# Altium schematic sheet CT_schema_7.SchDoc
size 278 x 170 mm
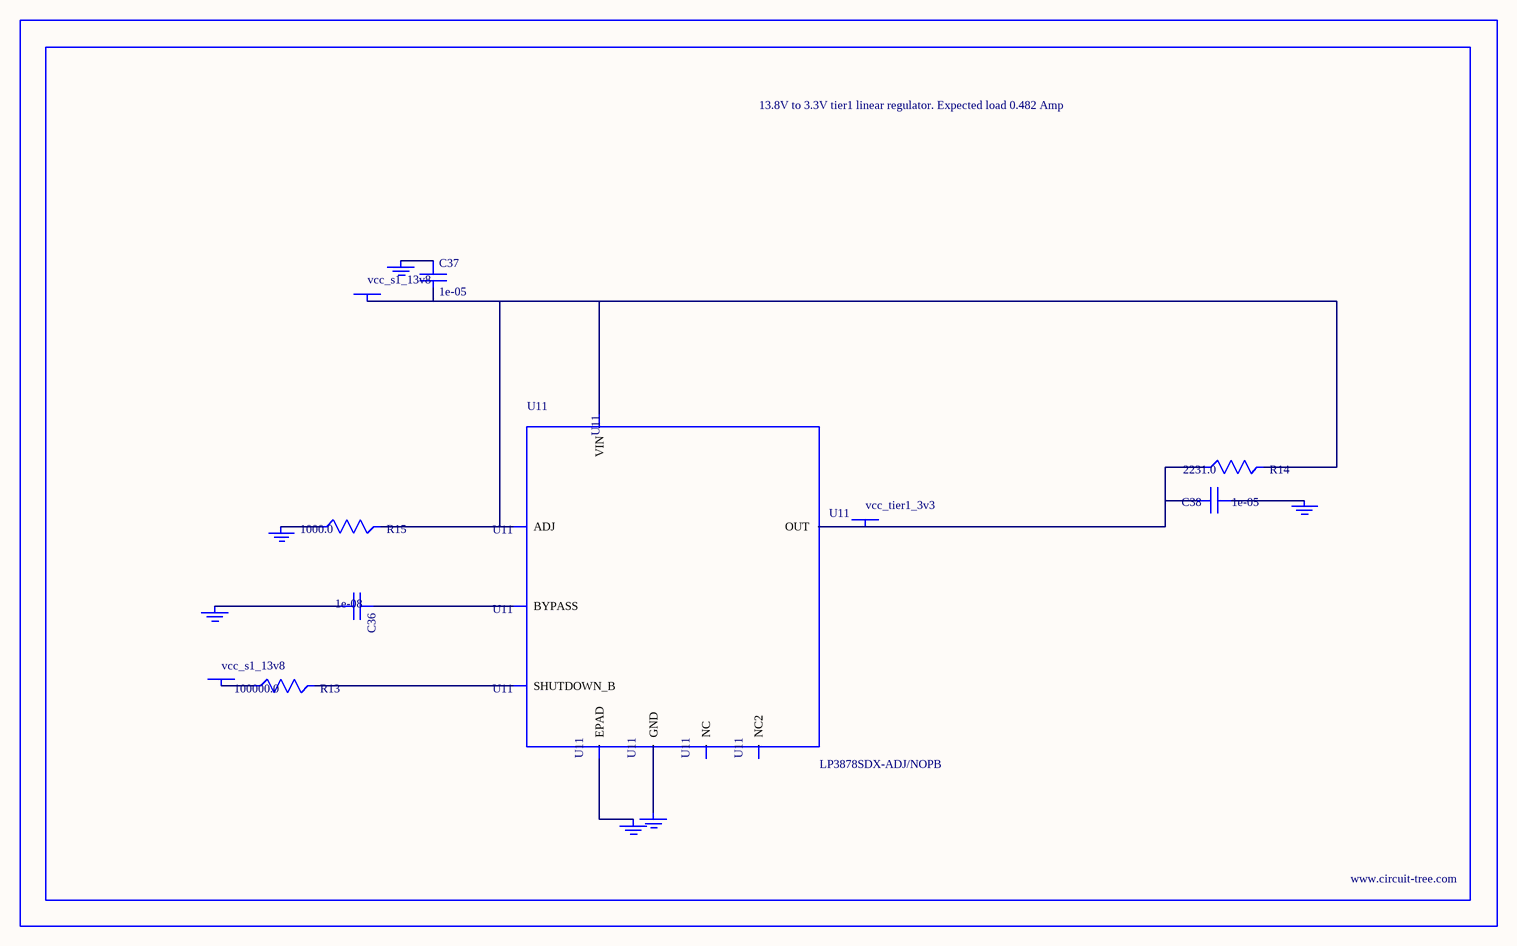
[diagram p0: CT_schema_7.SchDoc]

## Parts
BORDER6  (no value)
C36  1e-08  [C0402]
C37  1e-05  [C1210]
C38  1e-05  [C1210]
GND_INSTANCE_6_0  (no value)
GND_INSTANCE_6_1  (no value)
GND_INSTANCE_6_2  (no value)
GND_INSTANCE_6_3  (no value)
GND_INSTANCE_6_4  (no value)
GND_INSTANCE_6_5  (no value)
POWER_INSTANCE_6_0  vcc_s1_13v8
POWER_INSTANCE_6_1  vcc_s1_13v8
POWER_INSTANCE_6_2  vcc_tier1_3v3
R13  100000.0  [R0603]
R14  2231.0  [R0603]
R15  1000.0  [R0603]
U11  LP3878SDX-ADJ/NOPB  [WSON-8]

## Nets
NetC36_1: C36.1 U11.1(BYPASS)
NetC36_2: C36.2 GND_INSTANCE_6_0.0(GND)
NetC37_1: C37.1 GND_INSTANCE_6_1.0(GND)
NetC37_2: C37.2 POWER_INSTANCE_6_0.0(PWR) R14.2 R15.2 U11.4(VIN) U11.6(ADJ)
NetC38_1: C38.1 GND_INSTANCE_6_2.0(GND)
NetC38_2: C38.2 POWER_INSTANCE_6_2.0(PWR) R14.1 U11.5(OUT)
NetGND_INSTANCE_6_3_0: GND_INSTANCE_6_3.0(GND) R15.1
NetGND_INSTANCE_6_4_0: GND_INSTANCE_6_4.0(GND) U11.PAD(EPAD)
NetGND_INSTANCE_6_5_0: GND_INSTANCE_6_5.0(GND) U11.3(GND)
NetPOWER_INSTANCE_6_1_0: POWER_INSTANCE_6_1.0(PWR) R13.1
NetR13_2: R13.2 U11.8(SHUTDOWN_B)

Not connected (* = marked no-connect by the designer): U11 2(NC) 7(NC2)

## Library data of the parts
BORDER6 = BORDER_PAGE6
C36 = C0402C103K3RAC
C37 = C1210C106K5PACTU
C38 = GRM32DR61E106MA12L
GND_INSTANCE_6_0-GND_INSTANCE_6_5 = GND
POWER_INSTANCE_6_0-POWER_INSTANCE_6_2 = PWR
R13 = RC0603JR-07100KL
R14 = R14
R15 = RC0603JR-071KL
